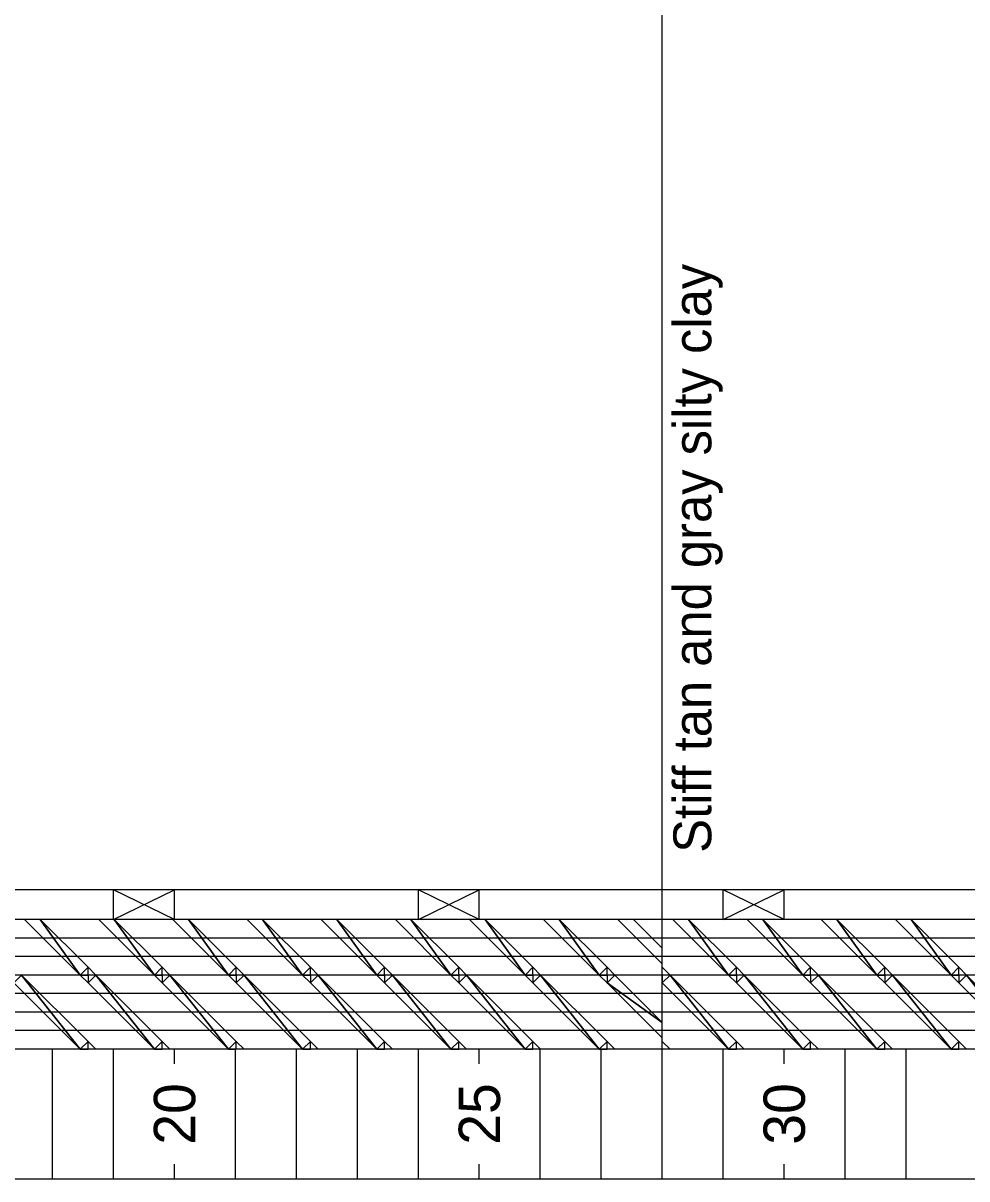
# Model space of a CAD drawing. Extents: x 1313964 to 1316843, y 2087046 to 2096619.
# Drawn here: x 1314106.81 to 1314122.29, y 2089818.7 to 2089837.67 of the extents above; entities that cross this region are included whole.
import ezdxf

# ---------------------------------------------------------------- set-up
doc = ezdxf.new("R2010")
doc.units = 0
doc.layers.add('B-Sub-Contour', color=7, linetype='Continuous')

msp = doc.modelspace()

# ---------------------------------------------------------------- linework, layer by layer
at = {"layer": 'B-Sub-Contour'}
for points in [[(1314136.725, 2089818.705), (1314136.725, 2089861.576), (1314075.306, 2089861.576), (1314075.306, 2089818.705), (1314136.725, 2089818.705)], [(1314117.292, 2089823.448), (1314117.292, 2089839.319)], [(1314134.292, 2089823.448), (1314089.292, 2089823.448)], [(1314108.292, 2089822.961), (1314109.292, 2089823.448)], [(1314109.292, 2089822.961), (1314108.292, 2089823.448)], [(1314108.292, 2089822.961), (1314108.292, 2089823.448)], [(1314109.292, 2089822.961), (1314109.292, 2089823.448)], [(1314113.292, 2089822.961), (1314114.292, 2089823.448)], [(1314114.292, 2089822.961), (1314113.292, 2089823.448)], [(1314113.292, 2089822.961), (1314113.292, 2089823.448)], [(1314114.292, 2089822.961), (1314114.292, 2089823.448)], [(1314117.292, 2089822.961), (1314117.292, 2089823.448)], [(1314118.292, 2089822.961), (1314119.292, 2089823.448)], [(1314119.292, 2089822.961), (1314118.292, 2089823.448)], [(1314118.292, 2089822.961), (1314118.292, 2089823.448)], [(1314119.292, 2089822.961), (1314119.292, 2089823.448)], [(1314134.292, 2089822.961), (1314082.603, 2089822.961)], [(1314117.292, 2089820.833), (1314117.292, 2089822.961)], [(1314117.292, 2089822.657), (1314101.792, 2089822.657)], [(1314132.292, 2089822.657), (1314117.292, 2089822.657)], [(1314117.292, 2089822.353), (1314101.792, 2089822.353)], [(1314132.292, 2089822.353), (1314117.292, 2089822.353)], [(1314117.292, 2089822.049), (1314101.792, 2089822.049)], [(1314132.292, 2089822.049), (1314117.292, 2089822.049)], [(1314117.292, 2089821.745), (1314101.792, 2089821.745)], [(1314132.292, 2089821.745), (1314117.292, 2089821.745)], [(1314117.292, 2089821.441), (1314101.792, 2089821.441)], [(1314132.292, 2089821.441), (1314117.292, 2089821.441)], [(1314117.292, 2089821.137), (1314101.792, 2089821.137)], [(1314132.292, 2089821.137), (1314117.292, 2089821.137)], [(1314134.292, 2089820.833), (1314082.603, 2089820.833)], [(1314107.292, 2089818.705), (1314107.292, 2089820.833)], [(1314107.292, 2089818.705), (1314107.292, 2089820.833)], [(1314108.292, 2089818.705), (1314108.292, 2089820.833)], [(1314109.292, 2089820.59), (1314109.292, 2089820.833)], [(1314109.292, 2089820.59), (1314109.292, 2089820.833)], [(1314110.292, 2089818.705), (1314110.292, 2089820.833)], [(1314111.292, 2089818.705), (1314111.292, 2089820.833)], [(1314111.292, 2089818.705), (1314111.292, 2089820.833)], [(1314112.292, 2089818.705), (1314112.292, 2089820.833)], [(1314113.292, 2089818.705), (1314113.292, 2089820.833)], [(1314113.292, 2089818.705), (1314113.292, 2089820.833)], [(1314114.292, 2089820.59), (1314114.292, 2089820.833)], [(1314115.292, 2089818.705), (1314115.292, 2089820.833)], [(1314115.292, 2089818.705), (1314115.292, 2089820.833)], [(1314116.292, 2089818.705), (1314116.292, 2089820.833)], [(1314117.292, 2089818.705), (1314117.292, 2089820.833)], [(1314117.292, 2089818.705), (1314117.292, 2089820.833)], [(1314118.292, 2089818.705), (1314118.292, 2089820.833)], [(1314119.292, 2089820.59), (1314119.292, 2089820.833)], [(1314119.292, 2089820.59), (1314119.292, 2089820.833)], [(1314120.292, 2089818.705), (1314120.292, 2089820.833)], [(1314121.292, 2089818.705), (1314121.292, 2089820.833)], [(1314121.292, 2089818.705), (1314121.292, 2089820.833)], [(1314109.292, 2089818.705), (1314109.292, 2089818.948)], [(1314109.292, 2089818.705), (1314109.292, 2089818.948)], [(1314114.292, 2089818.705), (1314114.292, 2089818.948)], [(1314119.292, 2089818.705), (1314119.292, 2089818.948)], [(1314119.292, 2089818.705), (1314119.292, 2089818.948)]]:
    msp.add_lwpolyline(points, dxfattribs=at)
for points in [[(1314107.746, 2089822.049), (1314107.089, 2089822.961), (1314106.834, 2089822.961), (1314107.746, 2089822.049)], [(1314107.746, 2089822.049), (1314107.874, 2089822.177), (1314107.089, 2089822.961), (1314107.746, 2089822.049)], [(1314108.962, 2089822.049), (1314108.305, 2089822.961), (1314108.05, 2089822.961), (1314108.962, 2089822.049)], [(1314108.962, 2089822.049), (1314109.09, 2089822.177), (1314108.305, 2089822.961), (1314108.962, 2089822.049)], [(1314110.178, 2089822.049), (1314109.521, 2089822.961), (1314109.266, 2089822.961), (1314110.178, 2089822.049)], [(1314110.178, 2089822.049), (1314110.306, 2089822.177), (1314109.521, 2089822.961), (1314110.178, 2089822.049)], [(1314111.394, 2089822.049), (1314110.738, 2089822.961), (1314110.482, 2089822.961), (1314111.394, 2089822.049)], [(1314111.394, 2089822.049), (1314111.522, 2089822.177), (1314110.738, 2089822.961), (1314111.394, 2089822.049)], [(1314112.611, 2089822.049), (1314111.954, 2089822.961), (1314111.698, 2089822.961), (1314112.611, 2089822.049)], [(1314112.611, 2089822.049), (1314112.738, 2089822.177), (1314111.954, 2089822.961), (1314112.611, 2089822.049)], [(1314113.827, 2089822.049), (1314113.17, 2089822.961), (1314112.915, 2089822.961), (1314113.827, 2089822.049)], [(1314113.827, 2089822.049), (1314113.955, 2089822.177), (1314113.17, 2089822.961), (1314113.827, 2089822.049)], [(1314115.043, 2089822.049), (1314114.386, 2089822.961), (1314114.131, 2089822.961), (1314115.043, 2089822.049)], [(1314115.043, 2089822.049), (1314115.171, 2089822.177), (1314114.386, 2089822.961), (1314115.043, 2089822.049)], [(1314116.259, 2089822.049), (1314115.603, 2089822.961), (1314115.347, 2089822.961), (1314116.259, 2089822.049)], [(1314116.259, 2089822.049), (1314116.387, 2089822.177), (1314115.603, 2089822.961), (1314116.259, 2089822.049)], [(1314116.819, 2089822.961), (1314116.563, 2089822.961), (1314117.292, 2089822.232), (1314117.292, 2089822.488)], [(1314118.381, 2089822.049), (1314117.724, 2089822.961), (1314117.468, 2089822.961), (1314118.381, 2089822.049)], [(1314118.381, 2089822.049), (1314118.509, 2089822.177), (1314117.724, 2089822.961), (1314118.381, 2089822.049)], [(1314119.597, 2089822.049), (1314118.94, 2089822.961), (1314118.685, 2089822.961), (1314119.597, 2089822.049)], [(1314119.597, 2089822.049), (1314119.725, 2089822.177), (1314118.94, 2089822.961), (1314119.597, 2089822.049)], [(1314120.813, 2089822.049), (1314120.157, 2089822.961), (1314119.901, 2089822.961), (1314120.813, 2089822.049)], [(1314120.813, 2089822.049), (1314120.941, 2089822.177), (1314120.157, 2089822.961), (1314120.813, 2089822.049)], [(1314122.03, 2089822.049), (1314121.373, 2089822.961), (1314121.117, 2089822.961), (1314122.03, 2089822.049)], [(1314122.03, 2089822.049), (1314122.157, 2089822.177), (1314121.373, 2089822.961), (1314122.03, 2089822.049)], [(1314107.746, 2089822.049), (1314107.874, 2089822.049), (1314107.874, 2089822.177), (1314107.746, 2089822.049)], [(1314108.001, 2089822.049), (1314107.874, 2089822.049), (1314107.874, 2089822.177), (1314108.001, 2089822.049)], [(1314108.962, 2089822.049), (1314109.09, 2089822.049), (1314109.09, 2089822.177), (1314108.962, 2089822.049)], [(1314109.217, 2089822.049), (1314109.09, 2089822.049), (1314109.09, 2089822.177), (1314109.217, 2089822.049)], [(1314110.178, 2089822.049), (1314110.306, 2089822.049), (1314110.306, 2089822.177), (1314110.178, 2089822.049)], [(1314110.434, 2089822.049), (1314110.306, 2089822.049), (1314110.306, 2089822.177), (1314110.434, 2089822.049)], [(1314111.394, 2089822.049), (1314111.522, 2089822.049), (1314111.522, 2089822.177), (1314111.394, 2089822.049)], [(1314111.65, 2089822.049), (1314111.522, 2089822.049), (1314111.522, 2089822.177), (1314111.65, 2089822.049)], [(1314112.611, 2089822.049), (1314112.738, 2089822.049), (1314112.738, 2089822.177), (1314112.611, 2089822.049)], [(1314112.866, 2089822.049), (1314112.738, 2089822.049), (1314112.738, 2089822.177), (1314112.866, 2089822.049)], [(1314113.827, 2089822.049), (1314113.955, 2089822.049), (1314113.955, 2089822.177), (1314113.827, 2089822.049)], [(1314114.082, 2089822.049), (1314113.955, 2089822.049), (1314113.955, 2089822.177), (1314114.082, 2089822.049)], [(1314115.043, 2089822.049), (1314115.171, 2089822.049), (1314115.171, 2089822.177), (1314115.043, 2089822.049)], [(1314115.298, 2089822.049), (1314115.171, 2089822.049), (1314115.171, 2089822.177), (1314115.298, 2089822.049)], [(1314116.259, 2089822.049), (1314116.387, 2089822.049), (1314116.387, 2089822.177), (1314116.259, 2089822.049)], [(1314116.515, 2089822.049), (1314116.387, 2089822.049), (1314116.387, 2089822.177), (1314116.515, 2089822.049)], [(1314117.42, 2089822.049), (1314117.292, 2089822.049), (1314117.292, 2089822.177), (1314117.42, 2089822.049)], [(1314118.381, 2089822.049), (1314118.509, 2089822.049), (1314118.509, 2089822.177), (1314118.381, 2089822.049)], [(1314118.636, 2089822.049), (1314118.509, 2089822.049), (1314118.509, 2089822.177), (1314118.636, 2089822.049)], [(1314119.597, 2089822.049), (1314119.725, 2089822.049), (1314119.725, 2089822.177), (1314119.597, 2089822.049)], [(1314119.853, 2089822.049), (1314119.725, 2089822.049), (1314119.725, 2089822.177), (1314119.853, 2089822.049)], [(1314120.813, 2089822.049), (1314120.941, 2089822.049), (1314120.941, 2089822.177), (1314120.813, 2089822.049)], [(1314121.069, 2089822.049), (1314120.941, 2089822.049), (1314120.941, 2089822.177), (1314121.069, 2089822.049)], [(1314122.03, 2089822.049), (1314122.157, 2089822.049), (1314122.157, 2089822.177), (1314122.03, 2089822.049)], [(1314122.285, 2089822.049), (1314122.157, 2089822.049), (1314122.157, 2089822.177), (1314122.285, 2089822.049)], [(1314107.746, 2089820.833), (1314106.785, 2089822.049), (1314106.657, 2089821.922), (1314107.746, 2089820.833)], [(1314107.746, 2089820.833), (1314107.874, 2089820.961), (1314106.785, 2089822.049), (1314107.746, 2089820.833)], [(1314107.874, 2089822.049), (1314107.874, 2089821.922), (1314107.746, 2089822.049), (1314107.874, 2089822.049)], [(1314108.001, 2089822.049), (1314107.874, 2089822.049), (1314107.874, 2089821.922), (1314108.001, 2089822.049)], [(1314108.962, 2089820.833), (1314108.001, 2089822.049), (1314107.874, 2089821.922), (1314108.962, 2089820.833)], [(1314108.962, 2089820.833), (1314109.09, 2089820.961), (1314108.001, 2089822.049), (1314108.962, 2089820.833)], [(1314109.09, 2089822.049), (1314109.09, 2089821.922), (1314108.962, 2089822.049), (1314109.09, 2089822.049)], [(1314109.217, 2089822.049), (1314109.09, 2089822.049), (1314109.09, 2089821.922), (1314109.217, 2089822.049)], [(1314110.178, 2089820.833), (1314109.217, 2089822.049), (1314109.09, 2089821.922), (1314110.178, 2089820.833)], [(1314110.178, 2089820.833), (1314110.306, 2089820.961), (1314109.217, 2089822.049), (1314110.178, 2089820.833)], [(1314110.306, 2089822.049), (1314110.306, 2089821.922), (1314110.178, 2089822.049), (1314110.306, 2089822.049)], [(1314110.434, 2089822.049), (1314110.306, 2089822.049), (1314110.306, 2089821.922), (1314110.434, 2089822.049)], [(1314111.394, 2089820.833), (1314110.434, 2089822.049), (1314110.306, 2089821.922), (1314111.394, 2089820.833)], [(1314111.394, 2089820.833), (1314111.522, 2089820.961), (1314110.434, 2089822.049), (1314111.394, 2089820.833)], [(1314111.522, 2089822.049), (1314111.522, 2089821.922), (1314111.394, 2089822.049), (1314111.522, 2089822.049)], [(1314111.65, 2089822.049), (1314111.522, 2089822.049), (1314111.522, 2089821.922), (1314111.65, 2089822.049)], [(1314112.611, 2089820.833), (1314111.65, 2089822.049), (1314111.522, 2089821.922), (1314112.611, 2089820.833)], [(1314112.611, 2089820.833), (1314112.738, 2089820.961), (1314111.65, 2089822.049), (1314112.611, 2089820.833)], [(1314112.738, 2089822.049), (1314112.738, 2089821.922), (1314112.611, 2089822.049), (1314112.738, 2089822.049)], [(1314112.866, 2089822.049), (1314112.738, 2089822.049), (1314112.738, 2089821.922), (1314112.866, 2089822.049)], [(1314113.827, 2089820.833), (1314112.866, 2089822.049), (1314112.738, 2089821.922), (1314113.827, 2089820.833)], [(1314113.827, 2089820.833), (1314113.955, 2089820.961), (1314112.866, 2089822.049), (1314113.827, 2089820.833)], [(1314113.955, 2089822.049), (1314113.955, 2089821.922), (1314113.827, 2089822.049), (1314113.955, 2089822.049)], [(1314114.082, 2089822.049), (1314113.955, 2089822.049), (1314113.955, 2089821.922), (1314114.082, 2089822.049)], [(1314115.043, 2089820.833), (1314114.082, 2089822.049), (1314113.955, 2089821.922), (1314115.043, 2089820.833)], [(1314115.043, 2089820.833), (1314115.171, 2089820.961), (1314114.082, 2089822.049), (1314115.043, 2089820.833)], [(1314115.171, 2089822.049), (1314115.171, 2089821.922), (1314115.043, 2089822.049), (1314115.171, 2089822.049)], [(1314115.298, 2089822.049), (1314115.171, 2089822.049), (1314115.171, 2089821.922), (1314115.298, 2089822.049)], [(1314116.259, 2089820.833), (1314115.298, 2089822.049), (1314115.171, 2089821.922), (1314116.259, 2089820.833)], [(1314116.259, 2089820.833), (1314116.387, 2089820.961), (1314115.298, 2089822.049), (1314116.259, 2089820.833)], [(1314116.387, 2089822.049), (1314116.387, 2089821.922), (1314116.259, 2089822.049), (1314116.387, 2089822.049)], [(1314116.515, 2089822.049), (1314116.387, 2089822.049), (1314116.387, 2089821.922), (1314116.515, 2089822.049)], [(1314116.387, 2089821.922), (1314117.292, 2089821.272), (1314116.515, 2089822.049), (1314116.387, 2089821.922)], [(1314117.42, 2089822.049), (1314117.292, 2089822.049), (1314117.292, 2089821.922), (1314117.42, 2089822.049)], [(1314118.381, 2089820.833), (1314117.42, 2089822.049), (1314117.292, 2089821.922), (1314118.381, 2089820.833)], [(1314118.381, 2089820.833), (1314118.509, 2089820.961), (1314117.42, 2089822.049), (1314118.381, 2089820.833)], [(1314118.509, 2089822.049), (1314118.509, 2089821.922), (1314118.381, 2089822.049), (1314118.509, 2089822.049)], [(1314118.636, 2089822.049), (1314118.509, 2089822.049), (1314118.509, 2089821.922), (1314118.636, 2089822.049)], [(1314119.597, 2089820.833), (1314118.636, 2089822.049), (1314118.509, 2089821.922), (1314119.597, 2089820.833)], [(1314119.597, 2089820.833), (1314119.725, 2089820.961), (1314118.636, 2089822.049), (1314119.597, 2089820.833)], [(1314119.725, 2089822.049), (1314119.725, 2089821.922), (1314119.597, 2089822.049), (1314119.725, 2089822.049)], [(1314119.853, 2089822.049), (1314119.725, 2089822.049), (1314119.725, 2089821.922), (1314119.853, 2089822.049)], [(1314120.813, 2089820.833), (1314119.853, 2089822.049), (1314119.725, 2089821.922), (1314120.813, 2089820.833)], [(1314120.813, 2089820.833), (1314120.941, 2089820.961), (1314119.853, 2089822.049), (1314120.813, 2089820.833)], [(1314120.941, 2089822.049), (1314120.941, 2089821.922), (1314120.813, 2089822.049), (1314120.941, 2089822.049)], [(1314121.069, 2089822.049), (1314120.941, 2089822.049), (1314120.941, 2089821.922), (1314121.069, 2089822.049)], [(1314122.03, 2089820.833), (1314121.069, 2089822.049), (1314120.941, 2089821.922), (1314122.03, 2089820.833)], [(1314122.03, 2089820.833), (1314122.157, 2089820.961), (1314121.069, 2089822.049), (1314122.03, 2089820.833)], [(1314122.157, 2089822.049), (1314122.157, 2089821.922), (1314122.03, 2089822.049), (1314122.157, 2089822.049)], [(1314122.285, 2089822.049), (1314122.157, 2089822.049), (1314122.157, 2089821.922), (1314122.285, 2089822.049)], [(1314123.246, 2089820.833), (1314122.285, 2089822.049), (1314122.157, 2089821.922), (1314123.246, 2089820.833)], [(1314123.246, 2089820.833), (1314123.373, 2089820.961), (1314122.285, 2089822.049), (1314123.246, 2089820.833)], [(1314116.387, 2089821.922), (1314117.292, 2089821.017), (1314117.292, 2089821.272), (1314116.387, 2089821.922)], [(1314107.746, 2089820.833), (1314107.874, 2089820.833), (1314107.874, 2089820.961), (1314107.746, 2089820.833)], [(1314108.001, 2089820.833), (1314107.874, 2089820.833), (1314107.874, 2089820.961), (1314108.001, 2089820.833)], [(1314108.962, 2089820.833), (1314109.09, 2089820.833), (1314109.09, 2089820.961), (1314108.962, 2089820.833)], [(1314109.217, 2089820.833), (1314109.09, 2089820.833), (1314109.09, 2089820.961), (1314109.217, 2089820.833)], [(1314110.178, 2089820.833), (1314110.306, 2089820.833), (1314110.306, 2089820.961), (1314110.178, 2089820.833)], [(1314110.434, 2089820.833), (1314110.306, 2089820.833), (1314110.306, 2089820.961), (1314110.434, 2089820.833)], [(1314111.394, 2089820.833), (1314111.522, 2089820.833), (1314111.522, 2089820.961), (1314111.394, 2089820.833)], [(1314111.65, 2089820.833), (1314111.522, 2089820.833), (1314111.522, 2089820.961), (1314111.65, 2089820.833)], [(1314112.611, 2089820.833), (1314112.738, 2089820.833), (1314112.738, 2089820.961), (1314112.611, 2089820.833)], [(1314112.866, 2089820.833), (1314112.738, 2089820.833), (1314112.738, 2089820.961), (1314112.866, 2089820.833)], [(1314113.827, 2089820.833), (1314113.955, 2089820.833), (1314113.955, 2089820.961), (1314113.827, 2089820.833)], [(1314114.082, 2089820.833), (1314113.955, 2089820.833), (1314113.955, 2089820.961), (1314114.082, 2089820.833)], [(1314115.043, 2089820.833), (1314115.171, 2089820.833), (1314115.171, 2089820.961), (1314115.043, 2089820.833)], [(1314115.298, 2089820.833), (1314115.171, 2089820.833), (1314115.171, 2089820.961), (1314115.298, 2089820.833)], [(1314116.259, 2089820.833), (1314116.387, 2089820.833), (1314116.387, 2089820.961), (1314116.259, 2089820.833)], [(1314116.515, 2089820.833), (1314116.387, 2089820.833), (1314116.387, 2089820.961), (1314116.515, 2089820.833)], [(1314117.42, 2089820.833), (1314117.292, 2089820.833), (1314117.292, 2089820.961), (1314117.42, 2089820.833)], [(1314118.381, 2089820.833), (1314118.509, 2089820.833), (1314118.509, 2089820.961), (1314118.381, 2089820.833)], [(1314118.636, 2089820.833), (1314118.509, 2089820.833), (1314118.509, 2089820.961), (1314118.636, 2089820.833)], [(1314119.597, 2089820.833), (1314119.725, 2089820.833), (1314119.725, 2089820.961), (1314119.597, 2089820.833)], [(1314119.853, 2089820.833), (1314119.725, 2089820.833), (1314119.725, 2089820.961), (1314119.853, 2089820.833)], [(1314120.813, 2089820.833), (1314120.941, 2089820.833), (1314120.941, 2089820.961), (1314120.813, 2089820.833)], [(1314121.069, 2089820.833), (1314120.941, 2089820.833), (1314120.941, 2089820.961), (1314121.069, 2089820.833)], [(1314122.03, 2089820.833), (1314122.157, 2089820.833), (1314122.157, 2089820.961), (1314122.03, 2089820.833)], [(1314122.285, 2089820.833), (1314122.157, 2089820.833), (1314122.157, 2089820.961), (1314122.285, 2089820.833)]]:
    msp.add_lwpolyline(points, close=True, dxfattribs=at)

# ---------------------------------------------------------------- texts
for s, height, p in [('Stiff tan and gray silty clay', 0.62209, (1314118.097, 2089824.056)), ('20', 0.6786, (1314109.632, 2089819.265)), ('20', 0.6786, (1314109.632, 2089819.265)), ('25', 0.6786, (1314114.632, 2089819.265)), ('30', 0.6786, (1314119.632, 2089819.265)), ('30', 0.6786, (1314119.632, 2089819.265))]:
    msp.add_text(s, height=height, rotation=90, dxfattribs=at).set_placement(p)

doc.saveas('drawing.dxf')
